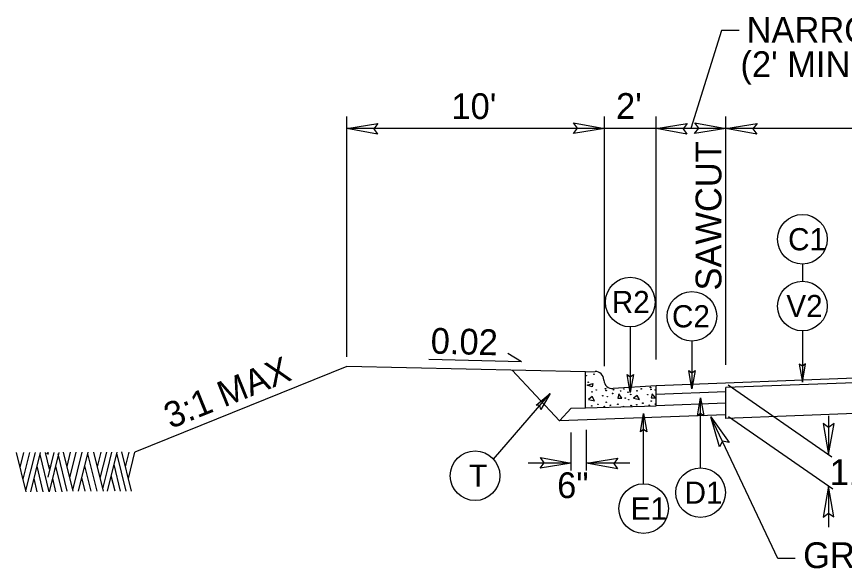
# Model space of a CAD drawing. Extents: x 573748 to 574632, y -54663 to -53209.
# Drawn here: x 573759.71 to 573807.89, y -53528.46 to -53496.33 of the extents above; entities that cross this region are included whole.
import ezdxf

# ---------------------------------------------------------------- set-up
doc = ezdxf.new("R2010")
doc.units = 0
for name, color, linetype in [('Prop Dimension', 7, 'Continuous'), ('Prop Dimension Text', 7, 'Continuous'), ('Prop Terminator CELL', 7, 'Continuous'), ('Typical Arrow Superelevation CELL', 7, 'Continuous'), ('Typical Curb CELL', 7, 'Continuous'), ('Typical Hinge Slope Arterial CELL', 7, 'Continuous'), ('Typical ID Circle CELL', 7, 'Continuous'), ('Typical Pavement Slope CELL', 7, 'Continuous'), ('Typical Slope Point Local CELL', 7, 'Continuous'), ('Typical Terminator CELL', 7, 'Continuous'), ('Typical Text ID Circle CELL', 7, 'Continuous')]:
    doc.layers.add(name, color=color, linetype=linetype)

msp = doc.modelspace()

# ---------------------------------------------------------------- linework, layer by layer
at = {"layer": 'Prop Dimension'}
for p, q in [((573778.926, -53516.133), (573778.926, -53502.153)), ((573793.926, -53516.685), (573793.926, -53502.153)), ((573796.926, -53516.292), (573796.926, -53502.153)), ((573800.984, -53516.603), (573800.984, -53502.153)), ((573793.926, -53502.845), (573778.926, -53502.845)), ((573796.926, -53502.845), (573793.926, -53502.845)), ((573800.984, -53502.845), (573796.926, -53502.845)), ((573820.484, -53502.845), (573800.984, -53502.845)), ((573832.366, -53516.757), (573800.984, -53517.931)), ((573801.117, -53517.766), (573807.152, -53521.96)), ((573832.366, -53518.556), (573800.984, -53519.73)), ((573800.984, -53519.73), (573800.984, -53519.509)), ((573801.142, -53519.618), (573807.207, -53523.834)), ((573806.963, -53519.576), (573806.963, -53521.829)), ((573791.99, -53522.75), (573791.99, -53520.546)), ((573792.881, -53522.75), (573792.881, -53520.399)), ((573791.99, -53522.328), (573789.485, -53522.328)), ((573795.392, -53522.328), (573792.881, -53522.328)), ((573806.963, -53523.664), (573806.963, -53526.067))]:
    msp.add_line(p, q, dxfattribs=at)
for points in [[(573801.753, -53497.145), (573800.732, -53497.145), (573798.955, -53502.845)], [(573805.026, -53527.882), (573804.005, -53527.882), (573800.121, -53519.626)]]:
    msp.add_lwpolyline(points, dxfattribs=at)
at = {"layer": 'Prop Terminator CELL'}
for points in [[(573780.722, -53503.179), (573778.926, -53502.845), (573780.74, -53502.549), (573780.506, -53502.866)], [(573792.129, -53502.512), (573793.926, -53502.845), (573792.111, -53503.142), (573792.345, -53502.825)], [(573798.722, -53503.179), (573796.926, -53502.845), (573798.74, -53502.549), (573798.506, -53502.866)], [(573799.188, -53502.512), (573800.984, -53502.845), (573799.17, -53503.142), (573799.404, -53502.825)], [(573802.781, -53503.179), (573800.984, -53502.845), (573802.799, -53502.549), (573802.564, -53502.866)], [(573800.607, -53521.387), (573800.121, -53519.626), (573801.182, -53521.128), (573800.794, -53521.056)], [(573806.653, -53520.029), (573806.963, -53521.829), (573807.283, -53520.019), (573806.963, -53520.249)], [(573790.194, -53521.995), (573791.99, -53522.328), (573790.176, -53522.625), (573790.41, -53522.308)], [(573794.677, -53522.662), (573792.881, -53522.328), (573794.695, -53522.032), (573794.461, -53522.349)], [(573807.273, -53525.465), (573806.963, -53523.664), (573806.643, -53525.475), (573806.963, -53525.245)]]:
    msp.add_lwpolyline(points, close=True, dxfattribs=at)
at = {"layer": 'Typical Arrow Superelevation CELL'}
for q in [(573783.694, -53516.289), (573788.306, -53515.953)]:
    msp.add_line((573789.086, -53516.432), q, dxfattribs=at)
at = {"layer": 'Typical Curb CELL'}
for p, q in [((573792.827, -53517.009), (573793.372, -53516.995)), ((573792.827, -53519.106), (573792.827, -53517.009)), ((573792.923, -53517.8), (573793.244, -53517.697)), ((573793.244, -53517.697), (573793.214, -53517.888)), ((573793.888, -53517.506), (573793.887, -53517.484)), ((573793.214, -53517.888), (573792.923, -53517.8)), ((573796.926, -53517.825), (573794.423, -53517.994)), ((573796.926, -53519), (573796.926, -53517.825)), ((573793.205, -53518.46), (573792.993, -53518.623)), ((573792.993, -53518.623), (573793.342, -53518.697)), ((573793.342, -53518.697), (573793.205, -53518.46)), ((573794.755, -53518.302), (573794.69, -53518.542)), ((573794.69, -53518.542), (573794.941, -53518.549)), ((573794.941, -53518.549), (573794.755, -53518.302)), ((573795.821, -53518.393), (573795.609, -53518.556)), ((573795.609, -53518.556), (573795.958, -53518.63)), ((573795.958, -53518.63), (573795.821, -53518.393)), ((573796.705, -53518.288), (573796.639, -53518.527)), ((573796.639, -53518.527), (573796.893, -53518.534)), ((573796.893, -53518.534), (573796.705, -53518.288)), ((573791.989, -53519.127), (573792.827, -53519.106)), ((573792.827, -53519.106), (573796.926, -53519))]:
    msp.add_line(p, q, dxfattribs=at)
for centre in [(573792.861, -53517.239), (573793.313, -53517.156), (573792.978, -53517.619), (573793.196, -53518.186), (573793.445, -53518.074), (573793.982, -53518), (573794.02, -53518.105), (573794.396, -53518.275), (573794.45, -53518.06), (573794.859, -53518.131), (573795.059, -53518.013), (573795.291, -53518.204), (573795.407, -53518.129), (573795.814, -53518.119), (573796.062, -53518.006), (573796.599, -53517.932), (573796.637, -53518.037), (573796.876, -53518.068), (573793.824, -53518.409), (573794.089, -53518.462), (573795.132, -53518.543), (573795.336, -53518.634), (573795.448, -53518.331), (573796.441, -53518.342), (573796.643, -53518.719), (573793.182, -53519), (573793.538, -53518.907), (573793.912, -53519.029), (573794.026, -53518.787), (573794.27, -53518.96), (573794.699, -53518.901), (573795.037, -53519.036), (573795.477, -53518.977), (573795.799, -53518.933), (573796.155, -53518.84), (573796.529, -53518.962), (573796.887, -53518.893)]:
    msp.add_circle(centre, 0.0168, dxfattribs=at)
for centre, start, end in [((573793.385, -53517.497), 1.4804, 91.4804), ((573794.39, -53517.493), 181.4804, 273.8649)]:
    msp.add_arc(centre, 0.502, start, end, dxfattribs=at)
at = {"layer": 'Typical Hinge Slope Arterial CELL'}
msp.add_line((573778.926, -53516.702), (573766.599, -53521.682), dxfattribs=at)
at = {"layer": 'Typical ID Circle CELL'}
for p, q in [((573805.443, -53510.739), (573805.443, -53511.744)), ((573795.424, -53514.396), (573795.424, -53518.222)), ((573805.443, -53514.63), (573805.443, -53517.616)), ((573799.009, -53515.225), (573799.009, -53517.997)), ((573787.46, -53522.095), (573790.766, -53518.274)), ((573799.513, -53522.607), (573799.513, -53518.523)), ((573796.201, -53523.534), (573796.201, -53519.45))]:
    msp.add_line(p, q, dxfattribs=at)
for centre in [(573805.443, -53509.297), (573795.424, -53512.953), (573805.443, -53513.187), (573799.009, -53513.783), (573786.393, -53523.066), (573799.513, -53524.049), (573796.201, -53524.976)]:
    msp.add_circle(centre, 1.443, dxfattribs=at)
at = {"layer": 'Typical Pavement Slope CELL'}
for p, q in [((573792.827, -53517.009), (573778.926, -53516.702)), ((573791.296, -53519.871), (573788.541, -53516.915)), ((573821.984, -53516.888), (573796.926, -53517.825)), ((573800.984, -53518.188), (573796.926, -53518.34)), ((573800.984, -53519.509), (573800.984, -53517.931)), ((573791.296, -53519.871), (573791.989, -53519.127)), ((573800.984, -53518.848), (573796.926, -53519)), ((573800.984, -53519.509), (573791.296, -53519.871))]:
    msp.add_line(p, q, dxfattribs=at)
at = {"layer": 'Typical Slope Point Local CELL'}
for p, q in [((573760.272, -53524), (573759.709, -53521.704)), ((573759.922, -53522.583), (573760.134, -53521.712)), ((573760.091, -53523.269), (573760.477, -53521.712)), ((573760.256, -53523.926), (573760.804, -53521.712)), ((573760.532, -53524), (573761.103, -53521.712)), ((573761.615, -53524), (573761.075, -53521.83)), ((573761.627, -53522.679), (573761.386, -53521.712)), ((573761.497, -53521.785), (573761.524, -53521.682)), ((573761.54, -53523.144), (573761.894, -53521.712)), ((573761.54, -53521.822), (573761.564, -53521.712)), ((573761.623, -53524), (573762.193, -53521.712)), ((573762.662, -53523.963), (573762.127, -53521.793)), ((573763.001, -53523.963), (573762.438, -53521.682)), ((573762.65, -53522.524), (573762.855, -53521.682)), ((573762.812, -53523.188), (573763.182, -53521.682)), ((573762.985, -53523.897), (573763.532, -53521.682)), ((573763.319, -53523.963), (573763.886, -53521.682)), ((573764.398, -53523.963), (573763.859, -53521.785)), ((573764.764, -53523.963), (573764.201, -53521.682)), ((573764.414, -53522.553), (573764.627, -53521.682)), ((573764.579, -53523.21), (573764.961, -53521.682)), ((573764.997, -53522.745), (573765.256, -53521.682)), ((573764.997, -53523.963), (573765.564, -53521.682)), ((573766.095, -53523.963), (573765.548, -53521.749)), ((573766.398, -53523.963), (573765.835, -53521.667)), ((573766.044, -53522.546), (573766.256, -53521.682)), ((573766.217, -53523.232), (573766.599, -53521.682)), ((573761.264, -53524), (573760.902, -53522.516)), ((573761.603, -53522.553), (573761.627, -53522.465)), ((573762.355, -53524), (573761.993, -53522.516)), ((573764.052, -53523.963), (573763.686, -53522.479)), ((573765.76, -53523.963), (573765.382, -53522.406)), ((573764.729, -53523.823), (573764.997, -53522.745)), ((573765.441, -53523.963), (573765.221, -53523.063)), ((573760.91, -53524), (573760.725, -53523.232)), ((573762.001, -53524), (573761.816, -53523.232)), ((573763.705, -53523.963), (573763.516, -53523.173))]:
    msp.add_line(p, q, dxfattribs=at)
at = {"layer": 'Typical Terminator CELL'}
for points in [[(573805.261, -53516.562), (573805.443, -53517.616), (573805.63, -53516.556), (573805.443, -53516.69)], [(573795.606, -53517.168), (573795.424, -53518.222), (573795.237, -53517.162), (573795.424, -53517.297)], [(573799.191, -53516.943), (573799.009, -53517.997), (573798.822, -53516.937), (573799.009, -53517.071)], [(573789.939, -53518.952), (573790.766, -53518.274), (573790.214, -53519.198), (573790.16, -53518.974)], [(573799.331, -53519.578), (573799.513, -53518.523), (573799.7, -53519.584), (573799.513, -53519.449)], [(573796.02, -53520.505), (573796.201, -53519.45), (573796.389, -53520.511), (573796.201, -53520.376)]]:
    msp.add_lwpolyline(points, close=True, dxfattribs=at)

# ---------------------------------------------------------------- texts
at = {"layer": 'Prop Dimension'}
msp.add_text('GRADE TO THIS LINE', height=1.5, rotation=360, dxfattribs=at).set_placement((573805.485, -53528.441))
at = {"layer": 'Prop Dimension Text'}
for s, p in [('NARROW WIDENING', (573802.194, -53497.852)), ("(2' MIN.)", (573801.835, -53499.852)), ("10'", (573785.017, -53502.296)), ("2'", (573794.596, -53502.288)), ('11"', (573807.035, -53523.603)), ('6"', (573791.169, -53524.367))]:
    msp.add_text(s, height=1.5, dxfattribs=at).set_placement(p)
for s, rotation, p in [('SAWCUT', 90, (573800.726, -53512.282)), ('0.02', 358.4883, (573783.794, -53515.95)), ('3:1 MAX', 21.9988, (573768.674, -53520.348))]:
    msp.add_text(s, height=1.5, rotation=rotation, dxfattribs=at).set_placement(p)
at = {"layer": 'Typical Text ID Circle CELL'}
for s, height, p in [('C1', 1.2912, (573804.607, -53509.94)), ('R2', 1.2912, (573794.346, -53513.596)), ('V2', 1.2912, (573804.506, -53513.83)), ('C2', 1.2912, (573797.851, -53514.426)), ('T', 1.291, (573786.043, -53523.709)), ('D1', 1.2912, (573798.585, -53524.692)), ('E1', 1.2912, (573795.449, -53525.619))]:
    msp.add_text(s, height=height, dxfattribs=at).set_placement(p)

doc.saveas('drawing.dxf')
